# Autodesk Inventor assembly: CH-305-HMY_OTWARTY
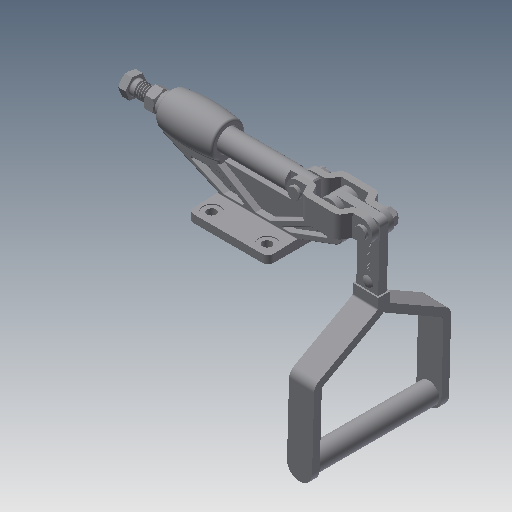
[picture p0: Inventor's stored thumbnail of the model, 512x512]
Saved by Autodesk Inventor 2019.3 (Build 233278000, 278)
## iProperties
Company: Î¢ÈíÖÐ¹ú
Created: 2015-08
Part Number: CH-305-HMY_OTWARTY
Material: Ogólny
Description: STEP AP203
Document SubType Name: Assembly
Designer: CADENGINEERING4
Sending System: SolidWorks 2012
Preprocessor: SwSTEP 2.0
Title: CH-305-HMY.STEP
Author: Î¢ÈíÓÃ»§
Revision Number: ÈÎºÎ
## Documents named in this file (13)
- D:\Vault_2016\Projekty\STRONA\Push-pull clamp\CH-305-HMY\CH-305-HMY_OTWARTY.iam
- D:\Vault_2016\Projekty\STRONA\Push-pull clamp\CH-305-HMY\CH-304-HM-01 BASE.ipt
- D:\Vault_2016\Projekty\STRONA\Push-pull clamp\CH-305-HMY\CH-304-HM-02 CREST STALK.ipt
- D:\Vault_2016\Projekty\STRONA\Push-pull clamp\CH-305-HMY\CH-304-HM-07.ipt
- D:\Vault_2016\Projekty\STRONA\Push-pull clamp\CH-305-HMY\CH-304-HM-04 CONNECTING-PLATE.ipt
- D:\Vault_2016\Projekty\STRONA\Push-pull clamp\CH-305-HMY\CH-304-HM-06.ipt
- D:\Vault_2016\Projekty\STRONA\Push-pull clamp\CH-305-HMY\304-05.ipt
- D:\Vault_2016\Projekty\STRONA\Push-pull clamp\CH-305-HMY\5-16 LOCK NUT.ipt
- D:\Vault_2016\Projekty\STRONA\Push-pull clamp\CH-305-HMY\M12 Nut.ipt
- D:\Vault_2016\Projekty\STRONA\Push-pull clamp\CH-305-HMY\CH-SA-125017 SPINDLE SUPPLIED.ipt
- D:\Vault_2016\Projekty\STRONA\Push-pull clamp\CH-305-HMY\CH-305-HMY HANDLE.ipt
- D:\Vault_2016\Projekty\STRONA\Push-pull clamp\CH-305-HMY\CH-305-HMY-06.ipt
- D:\Vault_2016\Projekty\STRONA\Push-pull clamp\CH-305-HMY\CH-305-HMY-087.ipt
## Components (16 placed, 16 different names)
1. CH-304-HM-01 BASE_1 — Zestawiające:14, Zestawiające:15, Zestawiające:20, Zestawiające:24, Zestawiające:29
2. CH-304-HM-02 CREST STALK_2 — Zestawiające:3, Zestawiające:4, Zestawiające:19, Zestawiające:20
3. CH-304-HM-07_3 — Zestawiające:12, Równoległe:3, Zestawiające:18
4. CH-304-HM-07_4 — Zestawiające:13, Równoległe:4, Zestawiające:15, Zestawiające:23
5. CH-304-HM-04 CONNECTING-PLATE_5 — Zestawiające:16, Zestawiające:17, Zestawiające:18, Zestawiające:19, Zestawiające:21, Zestawiające:25, Zestawiające:26, Zestawiające:27, Zestawiające:28
6. CH-304-HM-04 CONNECTING-PLATE_6 — Równoległe:1, Równoległe:2, Zestawiające:10, Zestawiające:11, Zestawiające:16, Zestawiające:17, Zestawiające:22
7. CH-304-HM-06_7 — Zestawiające:27, Zestawiające:28
8. 304-05_8 — Zestawiające:23, Zestawiające:24
9. CH-304-HM-06_9 — Zestawiające:25, Zestawiające:26
10. 5-16 LOCK NUT_10 — Równoległe:2, Zestawiające:11
11. 5-16 LOCK NUT_11 — Równoległe:1, Zestawiające:10
12. M12 Nut_12 — Zestawiające:1, Zestawiające:2, Zestawiające:3
13. CH-SA-125017 SPINDLE SUPPLIED_13 — Zestawiające:1, Zestawiające:2, Zestawiające:4
14. CH-305-HMY HANDLE_14 — Zestawiające:5, Zestawiające:6, Zestawiające:7, Zestawiające:8, Zestawiające:9, Zestawiające:12, Równoległe:3, Zestawiające:13, Równoległe:4, Zestawiające:14, Zestawiające:21, Zestawiające:22, Zestawiające:29
15. CH-305-HMY-06_15 — Zestawiające:5, Zestawiające:6, Zestawiające:7
16. CH-305-HMY-087_16 — Zestawiające:8, Zestawiające:9
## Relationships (33: Mate 29, Flush 4)
- Zestawiające:1 [Mate]: M12 Nut_12 ↔ CH-SA-125017 SPINDLE SUPPLIED_13
- Zestawiające:2 [Mate]: M12 Nut_12 ↔ CH-SA-125017 SPINDLE SUPPLIED_13
- Zestawiające:3 [Mate]: CH-304-HM-02 CREST STALK_2 ↔ M12 Nut_12
- Zestawiające:4 [Mate]: CH-304-HM-02 CREST STALK_2 ↔ CH-SA-125017 SPINDLE SUPPLIED_13
- Zestawiające:5 [Mate]: CH-305-HMY HANDLE_14 ↔ CH-305-HMY-06_15
- Zestawiające:6 [Mate]: CH-305-HMY HANDLE_14 ↔ CH-305-HMY-06_15
- Zestawiające:7 [Mate]: CH-305-HMY HANDLE_14 ↔ CH-305-HMY-06_15
- Zestawiające:8 [Mate]: CH-305-HMY HANDLE_14 ↔ CH-305-HMY-087_16
- Zestawiające:9 [Mate]: CH-305-HMY HANDLE_14 ↔ CH-305-HMY-087_16
- Równoległe:1 [Flush]: CH-304-HM-04 CONNECTING-PLATE_6 ↔ 5-16 LOCK NUT_11
- Równoległe:2 [Flush]: CH-304-HM-04 CONNECTING-PLATE_6 ↔ 5-16 LOCK NUT_10
- Zestawiające:10 [Mate]: CH-304-HM-04 CONNECTING-PLATE_6 ↔ 5-16 LOCK NUT_11
- Zestawiające:11 [Mate]: CH-304-HM-04 CONNECTING-PLATE_6 ↔ 5-16 LOCK NUT_10
- Zestawiające:12 [Mate]: CH-304-HM-07_3 ↔ CH-305-HMY HANDLE_14
- Równoległe:3 [Flush]: CH-304-HM-07_3 ↔ CH-305-HMY HANDLE_14
- Zestawiające:13 [Mate]: CH-304-HM-07_4 ↔ CH-305-HMY HANDLE_14
- Równoległe:4 [Flush]: CH-304-HM-07_4 ↔ CH-305-HMY HANDLE_14
- Zestawiające:14 [Mate]: CH-304-HM-01 BASE_1 ↔ CH-305-HMY HANDLE_14
- Zestawiające:15 [Mate]: CH-304-HM-01 BASE_1 ↔ CH-304-HM-07_4
- Zestawiające:16 [Mate]: CH-304-HM-04 CONNECTING-PLATE_5 ↔ CH-304-HM-04 CONNECTING-PLATE_6
- Zestawiające:17 [Mate]: CH-304-HM-04 CONNECTING-PLATE_5 ↔ CH-304-HM-04 CONNECTING-PLATE_6
- Zestawiające:18 [Mate]: CH-304-HM-07_3 ↔ CH-304-HM-04 CONNECTING-PLATE_5
- Zestawiające:19 [Mate]: CH-304-HM-02 CREST STALK_2 ↔ CH-304-HM-04 CONNECTING-PLATE_5
- Zestawiające:20 [Mate]: CH-304-HM-01 BASE_1 ↔ CH-304-HM-02 CREST STALK_2
- Zestawiające:21 [Mate]: CH-304-HM-04 CONNECTING-PLATE_5 ↔ CH-305-HMY HANDLE_14
- Zestawiające:22 [Mate]: CH-304-HM-04 CONNECTING-PLATE_6 ↔ CH-305-HMY HANDLE_14
- Zestawiające:23 [Mate]: CH-304-HM-07_4 ↔ 304-05_8
- Zestawiające:24 [Mate]: CH-304-HM-01 BASE_1 ↔ 304-05_8
- Zestawiające:25 [Mate]: CH-304-HM-04 CONNECTING-PLATE_5 ↔ CH-304-HM-06_9
- Zestawiające:26 [Mate]: CH-304-HM-04 CONNECTING-PLATE_5 ↔ CH-304-HM-06_9
- Zestawiające:27 [Mate]: CH-304-HM-04 CONNECTING-PLATE_5 ↔ CH-304-HM-06_7
- Zestawiające:28 [Mate]: CH-304-HM-04 CONNECTING-PLATE_5 ↔ CH-304-HM-06_7
- Zestawiające:29 [Mate]: CH-304-HM-01 BASE_1 ↔ CH-305-HMY HANDLE_14
